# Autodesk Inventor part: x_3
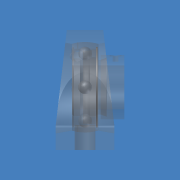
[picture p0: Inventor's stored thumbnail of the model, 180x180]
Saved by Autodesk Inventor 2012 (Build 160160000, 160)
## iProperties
Company: CAD-Verlag
Shininess: 64.0
Length Units: 11269
Angle Units: 11279
Time Units: 11290
Mass Units: 11283
Length Display Precision: 3
Angle Display Precision: 2
Compacted: True
Part Number: x_3
Document SubType Name: Modeling
Created: 2004-09
Material: Standard
Designer: Greiling
Manufacturer: Standard
Standards Organization: Custom
Density: 1 g/cm^3
Density: 0.0
Volumn: 0.0
Area: 0.0
PropertySet Name: Model Information
Control State: 0
Master: False
Checked Out: False
Übersetzungsnorm: STEP AP214CD
Dateiname: w2c22665.stp
Vorprozessor: ACIS
Postprozessor: Build: 081d, Release: 8 SP1 - Date: Tue 01/26/2004
Gesendete Einheiten: MILLIMETERS
Unbestimmtheit: 1e-06
Author: Jürgen Kronas
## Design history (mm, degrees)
feature "Basis1"
node "Volumenkörper1"
node "Volumenkörpern"
node "Oberflächenkörpern"
